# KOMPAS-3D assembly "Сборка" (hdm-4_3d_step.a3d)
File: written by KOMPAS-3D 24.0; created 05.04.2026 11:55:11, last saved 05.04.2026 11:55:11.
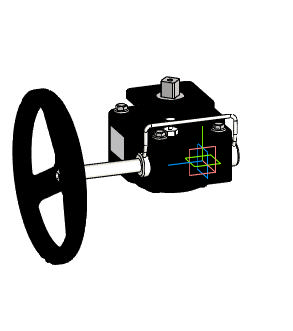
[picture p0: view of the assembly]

Document properties: Автор: R2D2; Полное имя файла: E:\Работа\Зайцев\Аксессуары для пневмоприводов\Ручной дублер DN.ru\MON4-1200-T54-ISO Ручной дублер DN.ru\исходные материалы\hdm-4_3d_step.a3d

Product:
- Component [detail]: Деталь1  | qty 1  | Автор: R2D2; source file: Деталь1 Деталь1.m3d
- Component [detail]: Деталь 2  | qty 1  | Автор: R2D2; source file: Деталь 2 Деталь 2.m3d
- Component [detail]: Bolt GB_T 16674.1 M14 x 40  | designation Bolt GB/T 16674.1 M14 x 40  | qty 1  | Автор: R2D2; source file: Bolt GB_T 16674.1 M14 x 40 Bolt GB_T 16674.1 M14 x 40.m3d
- Component [detail]: Bolt GB_T 16674.1 M14 x 40  | designation Bolt GB/T 16674.1 M14 x 40  | qty 3  | Комментарий: Hexagon  bolts with flang - Small series; Автор: R2D2; additional columns: Сталь, мягкая; source file: Bolt GB_T 16674.1 M14 x 40 Bolt GB_T 16674.1 M14 x 40.m3d
- Component [detail]: AS 1420 - 1973 - M6 x 10  | qty 1  | Автор: R2D2; source file: AS 1420 - 1973 - M6 x 10 AS 1420 - 1973 - M6 x 10.m3d
- Part/product: Сборка

Referenced files in E:\Работа\Зайцев\Аксессуары для пневмоприводов\Ручной дублер DN.ru\MON4-1200-T54-ISO Ручной дублер DN.ru\исходные материалы\: Деталь1 Деталь1.m3d, Деталь 2 Деталь 2.m3d, Bolt GB_T 16674.1 M14 x 40 Bolt GB_T 16674.1 M14 x 40.m3d, AS 1420 - 1973 - M6 x 10 AS 1420 - 1973 - M6 x 10.m3d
